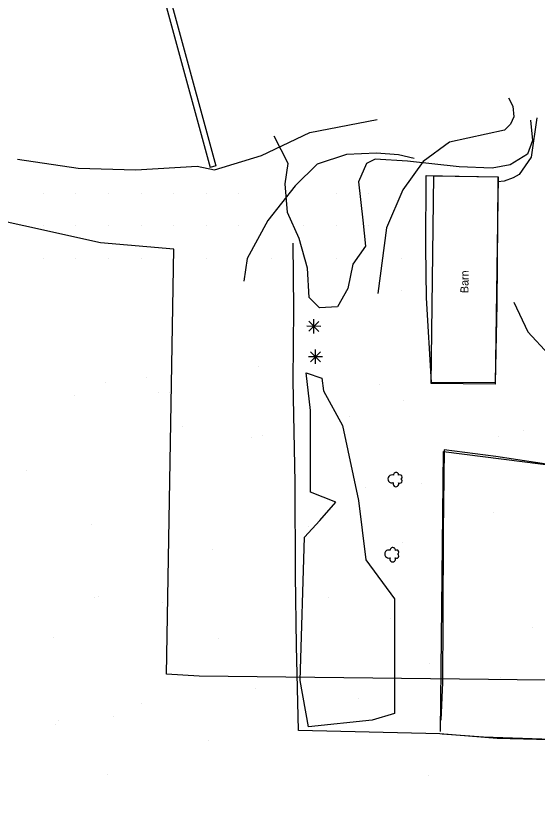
# Model space of a CAD drawing. Extents: x 19528164 to 19545171, y 7585743 to 7602745.
# Drawn here: x 19539188 to 19539508.5, y 7595102.9 to 7595584.1 of the extents above; entities that cross this region are included whole.
import ezdxf

# ---------------------------------------------------------------- set-up
doc = ezdxf.new("R2010")
doc.units = 0
for name, color, linetype in [('PhoBreakLine', 7, 'Continuous'), ('PhoBuilding', 7, 'Continuous'), ('PhoCulvert', 7, 'Continuous'), ('PhoFence', 7, 'Continuous'), ('PhoISAEPoints', 7, 'Continuous'), ('PhoNotesDesign', 7, 'Continuous'), ('PhoSurveyLimits', 7, 'Continuous'), ('PhoVegetation', 7, 'Continuous'), ('SurBreakLine', 7, 'Continuous'), ('SurEdgeEntranceUnpaved', 7, 'Continuous'), ('SurROWRail', 7, 'Continuous')]:
    doc.layers.add(name, color=color, linetype=linetype)

msp = doc.modelspace()

# ---------------------------------------------------------------- linework, layer by layer
at = {"layer": 'PhoBreakLine'}
for points in [[(19539490.8, 7595533.54), (19539493.49, 7595528.56), (19539494.02, 7595522), (19539492.08, 7595517.39), (19539488.27, 7595513.68), (19539454.6, 7595506.38), (19539438.4, 7595494.49), (19539425.88, 7595476.94), (19539415.74, 7595453.73), (19539410.58, 7595413.31)], [(19539490.8, 7595533.54), (19539493.49, 7595528.56), (19539494.02, 7595522), (19539492.08, 7595517.39), (19539488.27, 7595513.68), (19539454.6, 7595506.38), (19539438.4, 7595494.49), (19539425.88, 7595476.94), (19539415.74, 7595453.73), (19539410.58, 7595413.31)], [(19539189.15, 7595495.92), (19539226.37, 7595490.4), (19539261.85, 7595489.24), (19539299.57, 7595491.5), (19539310.16, 7595489.3), (19539339, 7595498.06), (19539368.82, 7595512.23), (19539410.06, 7595520.3)], [(19539432.73, 7595496.31), (19539423.19, 7595498.62), (19539409.65, 7595499.54), (19539391.19, 7595498.82), (19539373.14, 7595492.76), (19539359.63, 7595479.43), (19539343, 7595458.27), (19539330.32, 7595434.74), (19539328.09, 7595420.81)], [(19539440.38, 7595410.6), (19539439.97, 7595441.61), (19539440.11, 7595485.76), (19539460.48, 7595485.41), (19539484.21, 7595484.97), (19539484.34, 7595481.88), (19539483.68, 7595406.66)], [(19539440.38, 7595410.6), (19539439.97, 7595441.61), (19539440.11, 7595485.76), (19539460.48, 7595485.41), (19539484.21, 7595484.97), (19539484.34, 7595481.88), (19539483.68, 7595406.66)]]:
    msp.add_lwpolyline(points, dxfattribs=at)
at = {"layer": 'PhoBuilding'}
msp.add_lwpolyline([(19539443.24, 7595358.04), (19539444.88, 7595485.62), (19539484.39, 7595485.12), (19539482.61, 7595357.59)], close=True, dxfattribs=at)
msp.add_lwpolyline([(19539443.24, 7595358.04), (19539444.88, 7595485.62), (19539484.39, 7595485.12), (19539482.61, 7595357.59)], close=True, dxfattribs=at)
at = {"layer": 'PhoCulvert'}
for points in [[(19539263.97, 7595663.86), (19539260.59, 7595662.93), (19539307.54, 7595490.8)], [(19539263.97, 7595663.86), (19539310.93, 7595491.73), (19539307.54, 7595490.8)]]:
    msp.add_lwpolyline(points, dxfattribs=at)
at = {"layer": 'PhoFence'}
for points in [[(19539448.95, 7595143.91), (19539450.92, 7595316.25), (19539571.75, 7595300.74)], [(19539691.57, 7595314.14), (19539722.43, 7595315.55), (19539756.23, 7595222.69), (19539787.16, 7595137.43), (19539739.21, 7595138.01), (19539666.83, 7595138.56), (19539622.18, 7595138.42), (19539553.15, 7595137.91), (19539475.36, 7595140.46), (19539449.97, 7595142.4)]]:
    msp.add_lwpolyline(points, dxfattribs=at)
at = {"layer": 'PhoISAEPoints'}
for p, q in [((19539485, 7595495), (19539485, 7595495)), ((19539205, 7595475), (19539205, 7595475)), ((19539225, 7595475), (19539225, 7595475)), ((19539245, 7595475), (19539245, 7595475)), ((19539265, 7595475), (19539265, 7595475)), ((19539285, 7595475), (19539285, 7595475)), ((19539305, 7595475), (19539305, 7595475)), ((19539325, 7595475), (19539325, 7595475)), ((19539385, 7595475), (19539385, 7595475)), ((19539405, 7595475), (19539405, 7595475)), ((19539205, 7595455), (19539205, 7595455)), ((19539225, 7595455), (19539225, 7595455)), ((19539245, 7595455), (19539245, 7595455)), ((19539265, 7595455), (19539265, 7595455)), ((19539285, 7595455), (19539285, 7595455)), ((19539305, 7595455), (19539305, 7595455)), ((19539325, 7595455), (19539325, 7595455)), ((19539365, 7595455), (19539365, 7595455)), ((19539385, 7595455), (19539385, 7595455)), ((19539405, 7595455), (19539405, 7595455)), ((19539205, 7595435), (19539205, 7595435)), ((19539225, 7595435), (19539225, 7595435)), ((19539245, 7595435), (19539245, 7595435)), ((19539265, 7595435), (19539265, 7595435)), ((19539285, 7595435), (19539285, 7595435)), ((19539305, 7595435), (19539305, 7595435)), ((19539345, 7595435), (19539345, 7595435)), ((19539365, 7595435), (19539365, 7595435)), ((19539385, 7595435), (19539385, 7595435)), ((19539425, 7595435), (19539425, 7595435)), ((19539425, 7595415), (19539425, 7595415))]:
    msp.add_line(p, q, dxfattribs=at)
at = {"layer": 'PhoSurveyLimits'}
msp.add_lwpolyline([(19537599.9, 7594098.33), (19537715.33, 7594100.5), (19537804.6, 7593490.12), (19537804.6, 7593490.12), (19538635.74, 7593465.15), (19538635.74, 7593465.15), (19539208.61, 7594201.83), (19539787.71, 7594620.94), (19540254.76, 7595175), (19539748.45, 7595173.83), (19539673.98, 7595173.7), (19539300.81, 7595177.92), (19539280.61, 7595179.17), (19539285.1, 7595440.52), (19539240.17, 7595444.4), (19539053.39, 7595485.95), (19539048.98, 7595621.68)], dxfattribs=at)
at = {"layer": 'PhoVegetation'}
for p, q in [((19539374.31, 7595396.17), (19539368.04, 7595390.07)), ((19539374.31, 7595396.17), (19539368.04, 7595390.07)), ((19539374.23, 7595389.99), (19539368.12, 7595396.25)), ((19539374.23, 7595389.99), (19539368.12, 7595396.25)), ((19539371.12, 7595388.75), (19539371.23, 7595397.5)), ((19539371.12, 7595388.75), (19539371.23, 7595397.5)), ((19539375.55, 7595393.06), (19539366.8, 7595393.18)), ((19539375.55, 7595393.06), (19539366.8, 7595393.18)), ((19539371.17, 7595393.12), (19539371.17, 7595393.12)), ((19539371.17, 7595393.12), (19539371.17, 7595393.12)), ((19539375.36, 7595377.45), (19539369.09, 7595371.35)), ((19539375.28, 7595371.27), (19539369.17, 7595377.53)), ((19539372.17, 7595370.03), (19539372.28, 7595378.78)), ((19539376.6, 7595374.34), (19539367.85, 7595374.46)), ((19539372.23, 7595374.4), (19539372.23, 7595374.4))]:
    msp.add_line(p, q, dxfattribs=at)
for points in [[(19539504.21, 7595519.81), (19539505.45, 7595507.43), (19539502.41, 7595499.07), (19539491.83, 7595492.48), (19539480.79, 7595490.44), (19539460.42, 7595491.1), (19539428.69, 7595494.75), (19539408.81, 7595495.97), (19539403.53, 7595493.33), (19539398.58, 7595482.03), (19539401.24, 7595458.3), (19539402.95, 7595442.45), (19539395.16, 7595431.41), (19539392.03, 7595416.28), (19539385.67, 7595405), (19539374.61, 7595404.57), (19539368.22, 7595410.91), (19539367.36, 7595428.89), (19539362.27, 7595447.18), (19539355.05, 7595463.15), (19539353.53, 7595480.7), (19539355.4, 7595493.13), (19539346.87, 7595510.09)], [(19539504.21, 7595519.81), (19539505.45, 7595507.43), (19539502.41, 7595499.07), (19539491.83, 7595492.48), (19539480.79, 7595490.44), (19539460.42, 7595491.1), (19539428.69, 7595494.75), (19539408.81, 7595495.97), (19539403.53, 7595493.33), (19539398.58, 7595482.03), (19539401.24, 7595458.3), (19539402.95, 7595442.45), (19539395.16, 7595431.41), (19539392.03, 7595416.28), (19539385.67, 7595405), (19539374.61, 7595404.57), (19539368.22, 7595410.91), (19539367.36, 7595428.89), (19539362.27, 7595447.18), (19539355.05, 7595463.15), (19539353.53, 7595480.7), (19539355.4, 7595493.13), (19539346.87, 7595510.09)], [(19539377.06, 7595353.37), (19539388.9, 7595332.04), (19539398.69, 7595285.99), (19539403.07, 7595249.54), (19539420.74, 7595225.6), (19539420.77, 7595155.12), (19539407.03, 7595151.02), (19539367.92, 7595146.83), (19539362.76, 7595175.31), (19539365.42, 7595263.57), (19539374.96, 7595273.66), (19539384.72, 7595284.94), (19539369.06, 7595291.23), (19539369.13, 7595341.33), (19539366.51, 7595364.47), (19539376.13, 7595361.24), (19539377.06, 7595353.37), (19539377.06, 7595353.37)]]:
    msp.add_lwpolyline(points, dxfattribs=at)
for centre, radius, start, end in [((19539419.14, 7595299.32), 2.46, 67.4531, 291.043), ((19539421.68, 7595301.69), 1.6, 355.2463, 183.2499), ((19539424.04, 7595300.46), 1.34, 295.7722, 124.6514), ((19539421.61, 7595296.28), 1.76, 154.7305, 23.7656), ((19539424.05, 7595298.04), 1.34, 231.9982, 64.5704), ((19539419.71, 7595255.48), 1.6, 355.2463, 183.2499), ((19539417.17, 7595253.12), 2.46, 67.4531, 291.043), ((19539422.08, 7595251.84), 1.34, 231.9982, 64.5704), ((19539422.07, 7595254.25), 1.34, 295.7722, 124.6514), ((19539419.64, 7595250.07), 1.76, 154.7305, 23.7656)]:
    msp.add_arc(centre, radius, start, end, dxfattribs=at)
at = {"layer": 'SurBreakLine'}
for points in [[(19539490.8, 7595533.54), (19539493.49, 7595528.56), (19539494.02, 7595522), (19539492.08, 7595517.39), (19539488.27, 7595513.68), (19539454.6, 7595506.38), (19539438.4, 7595494.49), (19539425.88, 7595476.94), (19539415.74, 7595453.73), (19539410.58, 7595413.31)], [(19539440.38, 7595410.6), (19539439.97, 7595441.61), (19539440.11, 7595485.76), (19539460.48, 7595485.41), (19539484.21, 7595484.97), (19539484.34, 7595481.88), (19539483.68, 7595406.66)], [(19539597.39, 7595137.29), (19539540.44, 7595138.27), (19539483.89, 7595139.78), (19539448.63, 7595142.57), (19539361.69, 7595144.62), (19539360.44, 7595196.75), (19539359.96, 7595240.17), (19539359.67, 7595297.19), (19539358.54, 7595359.57), (19539358.93, 7595403.83), (19539358.48, 7595444.31)], [(19539483.68, 7595406.66), (19539482.69, 7595358.37), (19539443.5, 7595358.48), (19539440.38, 7595410.6)], [(19539572.18, 7595301.09), (19539520.9, 7595307.31), (19539483.03, 7595313), (19539451.34, 7595317.1), (19539450.73, 7595266.82), (19539450.4, 7595213.08), (19539450.25, 7595174.16), (19539449.17, 7595151.01)]]:
    msp.add_lwpolyline(points, dxfattribs=at)
at = {"layer": 'SurEdgeEntranceUnpaved'}
for p, q in [((19539336.9, 7595368.35), (19539336.9, 7595368.35)), ((19539243.04, 7595358.31), (19539243.04, 7595358.31)), ((19539268.52, 7595361.67), (19539268.52, 7595361.67)), ((19539411.26, 7595357.33), (19539411.26, 7595357.33)), ((19539224.22, 7595350.67), (19539224.22, 7595350.67)), ((19539275.72, 7595352.2), (19539275.72, 7595352.2)), ((19539282.29, 7595352.22), (19539282.29, 7595352.22)), ((19539426.24, 7595347.81), (19539426.24, 7595347.81)), ((19539393.03, 7595337.74), (19539393.03, 7595337.74)), ((19539290.68, 7595331.59), (19539290.68, 7595331.59)), ((19539500.08, 7595329.08), (19539500.08, 7595329.08)), ((19539332.68, 7595324.57), (19539332.68, 7595324.57)), ((19539339.6, 7595326.04), (19539339.6, 7595326.04)), ((19539484.35, 7595325.17), (19539484.35, 7595325.17)), ((19539194.91, 7595304.71), (19539194.91, 7595304.71)), ((19539437.29, 7595296.36), (19539437.29, 7595296.36)), ((19539402.92, 7595293.8), (19539402.92, 7595293.8)), ((19539481.82, 7595278.93), (19539481.82, 7595278.93)), ((19539234.36, 7595271.54), (19539234.36, 7595271.54)), ((19539367.91, 7595270.15), (19539367.91, 7595270.15)), ((19539425.39, 7595260.08), (19539425.39, 7595260.08)), ((19539308.73, 7595255.93), (19539308.73, 7595255.93)), ((19539236.66, 7595226.08), (19539236.66, 7595226.08)), ((19539238.57, 7595227.03), (19539238.57, 7595227.03)), ((19539278.34, 7595223.17), (19539278.34, 7595223.17)), ((19539380.36, 7595226.11), (19539380.36, 7595226.11)), ((19539418.29, 7595213.33), (19539418.29, 7595213.33)), ((19539505.57, 7595208.15), (19539505.57, 7595208.15)), ((19539211.01, 7595202.08), (19539211.01, 7595202.08)), ((19539312.46, 7595201.11), (19539312.46, 7595201.11)), ((19539442.2, 7595185.51), (19539442.2, 7595185.51)), ((19539485.78, 7595177.2), (19539485.78, 7595177.2)), ((19539335.44, 7595170.67), (19539335.44, 7595170.67)), ((19539265.6, 7595161.16), (19539265.6, 7595161.16)), ((19539398.8, 7595164.07), (19539398.8, 7595164.07)), ((19539214.12, 7595150.6), (19539214.12, 7595150.6)), ((19539248.03, 7595153.39), (19539248.03, 7595153.39)), ((19539212.57, 7595148.54), (19539212.57, 7595148.54)), ((19539306.52, 7595138.63), (19539306.52, 7595138.63)), ((19539244.5, 7595117.62), (19539244.5, 7595117.62)), ((19539441.47, 7595117.17), (19539441.47, 7595117.17))]:
    msp.add_line(p, q, dxfattribs=at)
at = {"layer": 'SurROWRail'}
for points in [[(19539508.13, 7595521.23), (19539504.67, 7595497.15), (19539497.36, 7595486.57), (19539493.61, 7595484.35), (19539488.12, 7595482.32), (19539484.34, 7595481.88)], [(19539494.02, 7595407.99), (19539502.74, 7595389.83), (19539515.61, 7595375.88), (19539539.21, 7595366.78), (19539560.58, 7595367.6), (19539584.8, 7595371.9), (19539614.09, 7595384.27), (19539638.23, 7595392.61)]]:
    msp.add_lwpolyline(points, dxfattribs=at)

# ---------------------------------------------------------------- texts
at = {"layer": 'PhoNotesDesign'}
msp.add_text('Barn', height=4.92, rotation=89.5617, dxfattribs=at).set_placement((19539466.16, 7595413.55))
msp.add_text('Barn', height=4.92, rotation=89.5617, dxfattribs=at).set_placement((19539466.16, 7595413.55))

doc.saveas('drawing.dxf')
